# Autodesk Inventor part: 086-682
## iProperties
Author: CM
Shininess: 31.0
Angle Display Precision: 2
Document Length Units: 11272
Document Angle Units: 11286
Document Time Units: 11279
Document Mass Units: 11290
Document Length Units Precision: 3
Document Angle Units Precision: 2
Compacted: True
PropertySet Name: _Private Model Information
Created: 2002-03
Part Number: 086-682
Material: Nylon-6/6
Description: SPAE-NAUR HD WIRE CLIP
Document SubType Name: Modeling
Designer: CM
Control State: 0
Master: False
Checked Out: False
PropertySet Name: Design Tracking Control
Density: 1.13
Volumn: 0.4200091006525341
Area: 6.592258505645575
PropertySet Name: Model Information
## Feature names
1. Extrusion2
2. Mirror1
3. Hole1
4. Fillet6
5. Fillet7
6. Fillet8
